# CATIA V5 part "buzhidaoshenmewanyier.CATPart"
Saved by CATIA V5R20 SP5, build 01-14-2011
Part number: 轴承
Bounding box of the stored display mesh (mm): x -100 to 100, y -99.999 to 99.999, z -2.5 to 19.843
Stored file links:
  E:\180222134\4\buzhidaoshenmewanyier.CATPart
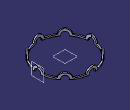
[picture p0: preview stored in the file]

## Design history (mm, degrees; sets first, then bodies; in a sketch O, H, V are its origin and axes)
Body1 (main body)
  Sketch1 on xy-plane, origin (0, 0, 0), H (1, 0, 0), V (0, 1, 0)
    circle A1 centre (0, 0) radius 100
    point P1 (100, 0)
    radius A1 = 100
    coincidence: A1 P1, P1 H
  Pad1: profile Sketch1, direction (0, 0, 1), length 2.5, mirrored extent, thin wall 5
  Body2
    Sketch2 on xy-plane, origin (0, 0, 0), H (1, 0, 0), V (0, 1, 0)
      arc A1 centre (97.5, 0) radius 20 from (97.5, -20) to (97.5, 20) ccw
      point P1 (97.5, 0)
      point P2 (117.5, 0)
      axis line L1 (97.5, 100) -> (97.5, -100)
      point P5 (97.5, 20)
      point P6 (97.5, -20)
      radius A1 = 20
      distance V L1 = 97.5
      distance V P1 = 97.5
      coincidence: P1 H, A1 P2, P2 H, L1 P5, L1 P6
      vertical: L1 V
    Shaft1: profile Sketch2, axis Sketch2.L1, angle 360
    CircPattern1: of Shaft1, instances 8, angular step 45, axis from face of Pad1
    Sketch3 on xy-plane, origin (0, 0, 0), H (1, 0, 0), V (0, 1, 0)
      circle A1 centre (0, 0) radius 95
      radius A1 = 95
    Pocket1: profile Sketch3, direction (0, 0, -1), length 30, mirrored extent
    Split1: SplitPlane end face of Pad1
    Sketch4 on xy-plane, origin (0, 0, 0), H (1, 0, 0), V (0, 1, 0)
      circle A1 centre (0, 0) radius 100
      point P1 (100, 0)
      radius A1 = 100
      coincidence: A1 P1, P1 H
    Pocket2: profile Sketch4, direction (0, 0, -1), length 30, mirrored extent, outer side
  Assemble1: tool Body2
  Body3
    Plane1: type Offset, RefPlane yz-plane, Offset 97.5
    Sketch5 on Plane1, origin (97.5, 0, 0), H (0, 1, 0), V (0, 0, 1)
      arc A1 centre (0, 0) radius 12 from (-12, 0) to (12, 0) ccw
      point P1 (0, 12)
      axis line L1 (-20, 0) -> (20, 0)
      point P2 (-20, 0)
      point P4 (-12, 0)
      point P5 (12, 0)
      radius A1 = 12
      coincidence: A1 P1, P1 V, P2 H, L1 P5, L1 P4
      horizontal: L1 H
    Shaft2: profile Sketch5, axis Sketch5.L1, angle 360
    CircPattern2: of Shaft2, instances 8, angular step 45, axis from face of Pad1
  Remove1: tool Body3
